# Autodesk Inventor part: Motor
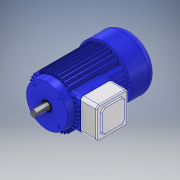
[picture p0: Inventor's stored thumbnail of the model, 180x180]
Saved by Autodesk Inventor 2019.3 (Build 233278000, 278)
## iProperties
Created: 2019-02
Part Number: Motor
Material: Ocel, měkká, svařovaná
Document SubType Name: Modeling
Designer: B-hon
Density: 7.85 g/cm^3
Appearance: Modrá – nástěnná malba – lesklá
Author: B-hon
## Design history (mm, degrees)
sketch "Náčrt1"
  geometry: C1 r 78 at (0, 0); 1 further point
  constraints: 1 centre point, 1 coincident
  dimensions: "d0" = 156 diameter of C1
extrude "Vysunutí1" new body sketch "Náčrt1" distance "d1" = 78; taper "d2" = 0 deg
fillet "Zaoblení1" dims "d3" = 25
sketch "Náčrt2" dims "d5" = 120
  geometry: L1 (0, 0)-(-74.744, 74.744); L2 (0, 0)-(105.704, 0); L3 (0, 0)-(-74.744, -74.744); L4 (0, 0)-(105.704, 0); L5 (-84.594, 42.426)-(-35.879, 42.426); L6 (-35.879, 42.426)-(-35.879, 39.426); L7 (-35.879, 39.426)-(-84.594, 39.426); L8 (-84.594, 39.426)-(-84.594, 42.426); C1 r 72.5 at (0, 0); 2 further points
  constraints: 16 end point, 3 horizontal, 2 coincident, 2 equal length, 2 parallel, 2 point on line, 1 centre point, 1 perpendicular, 3 other
  dimensions: "d4" = 145 diameter of C1; "d6" = 135 deg angle of L2 L1; "d7" = 135 deg angle of L3 L4; "d10" = 3 distance of L7.end L5.start
extrude "Vysunutí2" join sketch "Náčrt2" distance "d11" = 147; taper "d12" = 0 deg
pattern_linear "Obdélníkové pole1" dims "d15" = 10.23045
sketch "Náčrt3"
  geometry: C1 r 60 at (0, 0); C2 r 72.5 at (0, 0); C3 r 116.329 at (0, 0); 1 further point
  constraints: 3 centre point, 3 coincident
  dimensions: "d16" = 120 diameter of C1; "d17" = 145 diameter of C2
extrude "Vysunutí3" cut sketch "Náčrt3" extent not by distance; stored distance "d18" = 0; taper "d19" = 0 deg
pattern_circular "Kruhové pole1" dims angle "d21" = 360 deg
sketch "Náčrt4"
  geometry: C1 r 60 at (0, 0); 1 further point
  constraints: 1 centre point, 1 coincident
  dimensions: "d23" = 120 diameter of C1
extrude "Vysunutí4" join sketch "Náčrt4" distance "d24" = 147; taper "d25" = 0 deg
sketch "Náčrt6"
  geometry: C1 r 63.5 at (0, 0); 1 further point
  constraints: 1 centre point, 1 coincident
  dimensions: "d29" = 127 diameter of C1
node "Pracovní rovina1"
sketch "Náčrt7"
  geometry: C1 r 60 at (0, 0); 1 further point
  constraints: 1 centre point, 1 coincident
  dimensions: "d31" = 120 diameter of C1
feature "Šablonování1" sketch "Náčrt7" dims "d32" = 0, "d33" = 90 deg, "d34" = 0, "d35" = 90 deg
sketch "Náčrt8"
  geometry: L1 (0, 0)-(35.355, -35.355); L2 (0, 0)-(50, 0); 1 further point
  constraints: 4 end point, 1 coincident, 1 equal length, 1 horizontal
  dimensions: "d36" = 50 distance of L1.start L1.end; "d37" = 45 deg angle of L1 L2
hole "Díra1" sketch "Náčrt8" at (35.355, -35.355) diameter "d38" = 4.917; stored, may be unused: countersink angle "d42" = 90 deg, drill point angle "d44" = 118 deg; dims "d39" = 12, "d40" = 6, "d41" = 2, "d43" = 17.1
pattern_circular "Kruhové pole2" dims angle "d46" = 360 deg
sketch "Náčrt9"
  geometry: C1 r 9.5 at (0, 0); 1 further point
  constraints: 1 centre point, 1 coincident
  dimensions: "d48" = 19 diameter of C1
extrude "Vysunutí6" join sketch "Náčrt9" distance "d49" = 40; taper "d50" = 0 deg
sketch "Náčrt10"
  geometry: C1 r 9.5 at (0, 0); C2 r 9.5 at (0, 0) reference; C3 r 15 at (0, 0); 1 further point
  constraints: 2 centre point, 2 coincident
  dimensions: "d51" = 19 diameter of C1; "d52" = 30 diameter of C3
extrude "Vysunutí7" cut sketch "Náčrt10" distance "d53" = 0.5; taper "d54" = 0 deg
node "Pracovní rovina2"
sketch "Náčrt11"
  geometry: L1 (0, 10.699)-(0, 30.569); L2 (3, 10.699)-(3, 30.569); L3 (-3, 30.569)-(-3, 10.699); A1 r 3 centre (0, 10.699) between (-3, 10.699) and (3, 10.699); A2 r 3 centre (0, 30.569) between (3, 30.569) and (-3, 30.569); 2 further points
  constraints: 8 end point, 4 point on circle, 4 tangent, 2 centre point, 1 midpoint, 1 parallel, 1 vertical
  dimensions: "d55" = 6 diameter of A2
extrude "Vysunutí8" cut sketch "Náčrt11" distance "d56" = 3; taper "d57" = 0 deg
chamfer "Zkosení1" distance "d58" = 1; stored, may be unused: second distance "d59" = 2, angle "d60" = 45 deg
sketch "Náčrt12" dims "d69" = 10, "d76" = 10, "d83" = 10, "d90" = 10, "d97" = 10
  geometry: L1 (-4, -26)-(4, -26); L2 (4, -26)-(4, -18); L3 (4, -18)-(-4, -18); L4 (-4, -18)-(-4, -26); L5 (-4, -26)-(4, -18); L6 (4, -26)-(-4, -18); L7 (-4, -38)-(4, -38); L8 (4, -38)-(4, -30); L9 (4, -30)-(-4, -30); L10 (-4, -30)-(-4, -38); L11 (-4, -38)-(4, -30); L12 (4, -38)-(-4, -30); L13 (-4, -50)-(4, -50); L14 (4, -50)-(4, -42); L15 (4, -42)-(-4, -42); L16 (-4, -42)-(-4, -50); L17 (-4, -50)-(4, -42); L18 (4, -50)-(-4, -42); L19 (16, -38)-(16, -30); L20 (8, -30)-(8, -38); L21 (8, -38)-(16, -30); L22 (16, -38)-(8, -30); L23 (8, -38)-(16, -38); L24 (16, -42)-(8, -42); L25 (16, -50)-(16, -42); L26 (8, -42)-(8, -50); L27 (8, -50)-(16, -42); L28 (16, -50)-(8, -42); L29 (8, -50)-(16, -50); L30 (16, -30)-(8, -30); L31 (8, -26)-(16, -26); L32 (16, -26)-(16, -18); L33 (16, -18)-(8, -18); L34 (8, -18)-(8, -26); L35 (8, -26)-(16, -18); L36 (16, -26)-(8, -18); L37 (28, -30)-(20, -30); L38 (20, -26)-(28, -26); L39 (28, -26)-(28, -18); L40 (28, -18)-(20, -18); L41 (20, -26)-(28, -18); L42 (28, -26)-(20, -18); L43 (20, -18)-(20, -26); L44 (20, -30)-(20, -38); L45 (28, -38)-(28, -30); L46 (20, -38)-(28, -30); L47 (28, -38)-(20, -30); L48 (20, -38)-(28, -38); L49 (32, -18)-(32, -26); L50 (32, -26)-(40, -26); L51 (40, -26)-(40, -18); L52 (32, -26)-(40, -18); L53 (40, -26)-(32, -18); L54 (40, -18)-(32, -18); L55 (20, -14)-(28, -14); L56 (20, -6)-(20, -14); L57 (28, -6)-(20, -6); L58 (20, -14)-(28, -6); L59 (28, -14)-(20, -6); L60 (28, -14)-(28, -6); L61 (32, -6)-(32, -14); L62 (32, -14)-(40, -14); L63 (40, -14)-(40, -6); L64 (40, -14)-(32, -6)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; C1 r 15 at (0, 0); 12 further points
  constraints: 132 end point, 22 midpoint, 5 collinear, 4 horizontal, 2 parallel, 2 vertical, 1 centre point, 1 coincident, 1 perpendicular, 105 other
  dimensions: "d61" = 30 diameter of C1; "d62" = 8 distance of L3.end L2.end; "d63" = 8 distance of L2.end L1.end; "d66" = 12 distance of L1.start L7.start; "d73" = 12 distance of point (0, -34) point (12, -34); "d80" = 12 distance of L19.end L37.start; "d87" = 12 distance of L38.start L49.end; "d94" = 12 distance of L38.end L55.end; "d99" = 18 distance from line of L3 point (0, 0)
extrude "Vysunutí9" cut sketch "Náčrt12" distance "d100" = 3; taper "d101" = 0 deg
sketch "Náčrt13"
  geometry: C1 r 15 at (0, 0); 1 further point
  constraints: 1 centre point, 1 coincident
  dimensions: "d102" = 30 diameter of C1
extrude "Vysunutí10" join sketch "Náčrt13" distance "d103" = 1; taper "d104" = 0 deg
pattern_circular "Kruhové pole3" dims angle "d106" = 360 deg
sketch "Náčrt14"
  geometry: C1 r 54 at (26, 16); 1 further point
  constraints: 1 centre point, 1 coincident
  dimensions: "d108" = 108 diameter of C1
extrude "Vysunutí11" cut sketch "Náčrt14" distance "d109" = 35; taper "d110" = 0 deg
node "Pracovní rovina3"
sketch "Náčrt15"
  geometry: L1 (45.5, 128.677)-(-45.5, 128.677); L2 (-45.5, 128.677)-(-45.5, 219.677); L3 (-45.5, 219.677)-(45.5, 219.677); L4 (45.5, 219.677)-(45.5, 128.677); L5 (45.5, 128.677)-(-45.5, 219.677); L6 (-45.5, 128.677)-(45.5, 219.677); 2 further points
  constraints: 12 end point, 2 midpoint, 2 parallel, 1 horizontal, 1 perpendicular
  dimensions: "d112" = 91 distance of L2.end L3.end; "d113" = 91 distance of L1.end L2.end
extrude "Vysunutí12" join sketch "Náčrt15" distance "d114" = 50; taper "d115" = 0 deg
sketch "Náčrt16"
  geometry: L1 (-128.677, 45.5)-(-128.677, -45.5) reference; L2 (-219.677, 45.5)-(-128.677, 45.5) reference; L3 (-219.677, -45.5)-(-219.677, 45.5) reference; L4 (-128.677, -45.5)-(-219.677, -45.5) reference; L5 (-138.677, -25.5)-(-138.677, 25.5); L6 (-148.677, 35.5)-(-199.677, 35.5); L7 (-209.677, 25.5)-(-209.677, -25.5); L8 (-199.677, -35.5)-(-148.677, -35.5); L9 (-148.677, 35.5)-(-138.677, 25.5); L10 (-199.677, 35.5)-(-209.677, 25.5); L11 (-209.677, -25.5)-(-199.677, -35.5); L12 (-138.677, -25.5)-(-148.677, -35.5); 5 further points
  constraints: 16 end point, 8 point on line, 3 other
  dimensions: "d116" = 10 distance between parallel lines of L1 L5; "d117" = 10 distance of L6.start point (-138.677, 35.5); "d118" = 10 distance of L5.end point (-138.677, 35.5) (= d117); "d119" = 10 distance of L6.end point (-209.677, 35.5) (= d117); "d120" = 10 distance of L7.start point (-209.677, 35.5) (= d119); "d121" = 10 distance of L7.end point (-209.677, -35.5) (= d117); "d122" = 10 distance of L8.start point (-209.677, -35.5) (= d121); "d123" = 10 distance of L5.start point (-138.677, -35.5) (= d117); "d124" = 10 distance of L8.end point (-138.677, -35.5) (= d123)
extrude "Vysunutí13" cut sketch "Náčrt16" distance "d125" = 3; taper "d126" = 0 deg
fillet "Zaoblení2" dims "d127" = 8
fillet "Zaoblení3" dims "d128" = 3
fillet "Zaoblení4" dims "d129" = 3
sketch "Náčrt17"
  geometry: L1 (136.677, 45.5)-(211.677, 45.5) reference; L2 (128.677, -37.5)-(128.677, 37.5) reference; L3 (211.677, -45.5)-(136.677, -45.5) reference; L4 (219.677, 37.5)-(219.677, -37.5) reference; L5 (136.677, 46.5)-(211.677, 46.5); L6 (220.677, 37.5)-(220.677, -37.5); L7 (211.677, -46.5)-(136.677, -46.5); L8 (127.677, -37.5)-(127.677, 37.5); A1 r 8 centre (136.677, 37.5) between (136.677, 45.5) and (128.677, 37.5) reference; A2 r 8 centre (136.677, -37.5) between (128.677, -37.5) and (136.677, -45.5) reference; A3 r 8 centre (211.677, -37.5) between (211.677, -45.5) and (219.677, -37.5) reference; A4 r 8 centre (211.677, 37.5) between (219.677, 37.5) and (211.677, 45.5) reference; A5 r 9 centre (136.677, 37.5) between (136.677, 46.5) and (127.677, 37.5); A6 r 9 centre (211.677, 37.5) between (220.677, 37.5) and (211.677, 46.5); A7 r 9 centre (211.677, -37.5) between (211.677, -46.5) and (220.677, -37.5); A8 r 9 centre (136.677, -37.5) between (127.677, -37.5) and (136.677, -46.5); 1 further point
  constraints: 8 end point, 8 point on circle, 4 centre point, 7 other
  dimensions: "d130" = 1 distance between parallel lines of L2 L8
extrude "Vysunutí14" join sketch "Náčrt17" distance "d131" = 30; taper "d132" = 0 deg
node "Těleso1"
node "Promítnutá smyčka1"
other parameters: "d111" = 123
